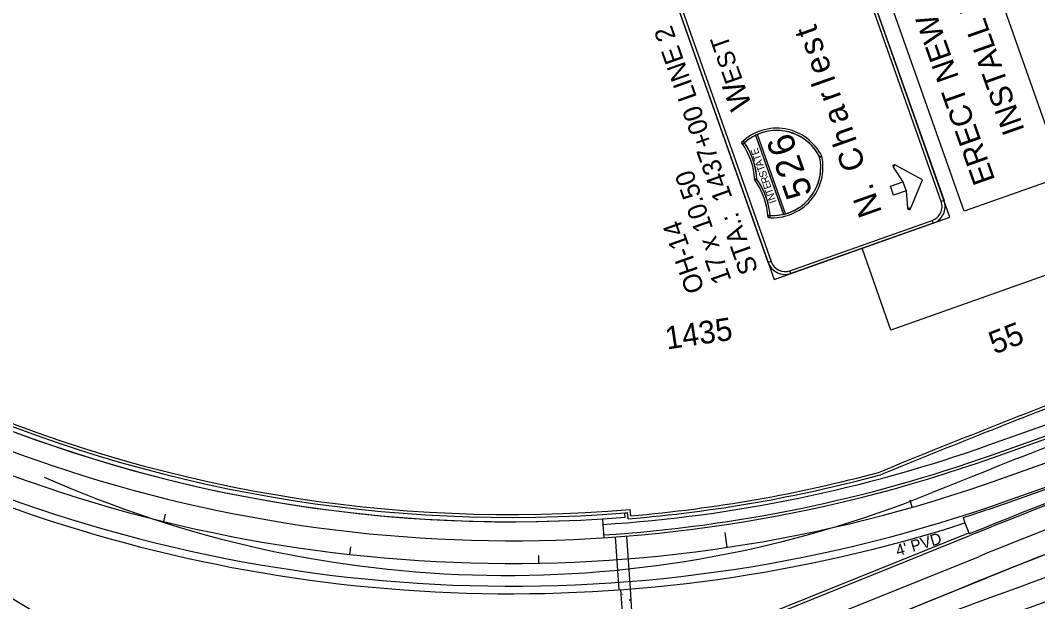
# Model space of a CAD drawing. Extents: x 2338610 to 2351914, y 366540 to 376484.
# Drawn here: x 2349299 to 2349836, y 368231 to 368538 of the extents above; entities that cross this region are included whole.
import ezdxf

# ---------------------------------------------------------------- set-up
doc = ezdxf.new("R2010")
doc.units = 0
for name, color, linetype in [('RD_HC_Cl', 7, 'Continuous'), ('RD_HC_CL_Rel', 7, 'Continuous'), ('RD_PD_ConcMed', 7, 'Continuous'), ('RD_PD_Final_LnLine', 7, 'Continuous'), ('RD_PD_Final_TrvlWay', 7, 'Continuous'), ('RD_PD_FOC', 7, 'Continuous'), ('RD_PD_GR', 7, 'Continuous'), ('RD_PD_MedBWall', 7, 'Continuous'), ('RD_PD_NOISE-WALL-GM', 7, 'Continuous'), ('RD_PD_PaveShd', 7, 'Continuous'), ('RD_PD_SW', 7, 'Continuous'), ('RD_PD_WallCut', 7, 'Continuous'), ('TR PM UNASSIGNED 3', 7, 'Continuous'), ('TR SN EXTRUDED PANEL SIGNS - GROUND MOUNTED', 7, 'Continuous'), ('TR SN EXTRUDED PANEL SIGNS- MOUNTED OVERHEAD', 7, 'Continuous'), ('TR SN UNASSIGNED 7', 7, 'Continuous')]:
    doc.layers.add(name, color=color, linetype=linetype)

msp = doc.modelspace()

# ---------------------------------------------------------------- linework, layer by layer
at = {"layer": 'RD_HC_Cl'}
for centre, radius, start, end in [((2351947.82, 362927.74), 5782.08, 109.588035, 112.01473), ((2351947.82, 362927.74), 5782.08, 109.588035, 112.01473), ((2351947.82, 362927.74), 5782.08, 109.588035, 112.01473), ((2351947.82, 362927.74), 5782.08, 109.588035, 112.01473), ((2351947.82, 362927.74), 5729.58, 109.588035, 115.940729), ((2349555.53, 368844.49), 600, 245.9774, 292.01473), ((2349555.53, 368844.49), 600, 245.9774, 292.01473), ((2349555.53, 368844.49), 600, 245.9774, 292.01473), ((2349555.53, 368844.49), 600, 245.9774, 292.01473)]:
    msp.add_arc(centre, radius, start, end, dxfattribs=at)
at = {"layer": 'RD_HC_CL_Rel'}
msp.add_line((2349816.74, 368295.51), (2350102.51, 368397.2), dxfattribs=at)
for centre, radius, start, end in [((2349557.92, 369022.83), 772, 245.88247, 289.58804), ((2344717.52, 360471.2), 9000, 59.178507, 60.642806)]:
    msp.add_arc(centre, radius, start, end, dxfattribs=at)
at = {"layer": 'RD_PD_ConcMed'}
for p, q in [((2349821.09, 368283.26), (2350106.87, 368384.95)), ((2349796.76, 368275.05), (2349797.67, 368272.19)), ((2349799.79, 368266.92), (2349799.97, 368266.46))]:
    msp.add_line(p, q, dxfattribs=at)
for centre, radius, start, end in [((2351947.82, 362927.74), 5754.58, 109.588035, 111.915714), ((2349557.92, 369022.83), 785, 287.713, 289.58804)]:
    msp.add_arc(centre, radius, start, end, dxfattribs=at)
at = {"layer": 'RD_PD_Final_LnLine'}
for p, q in [((2349815.51, 368295.11), (2350101.29, 368396.8)), ((2349612.85, 368264.87), (2349614.76, 368236.93)), ((2349618.83, 368265.28), (2349620.74, 368237.34)), ((2349685.87, 368206.54), (2349804.82, 368254.4)), ((2349690.35, 368195.41), (2349809.3, 368243.27))]:
    msp.add_line(p, q, dxfattribs=at)
for centre, radius, start, end in [((2349557.92, 369022.83), 772, 245.88247, 289.58804), ((2351947.82, 362927.74), 5741.58, 110.240054, 111.915714), ((2351947.82, 362927.74), 5729.58, 110.561472, 111.915714), ((2351783.35, 362853.29), 5729.58, 109.588035, 115.940729), ((2351783.35, 362853.29), 5717.58, 109.58804, 115.94073)]:
    msp.add_arc(centre, radius, start, end, dxfattribs=at)
at = {"layer": 'RD_PD_Final_TrvlWay'}
for p, q in [((2349812.71, 368306.81), (2350098.11, 368408.37)), ((2349820.76, 368284.2), (2350106.54, 368385.9)), ((2349681.39, 368217.67), (2349800.35, 368265.53))]:
    msp.add_line(p, q, dxfattribs=at)
for centre, radius, start, end in [((2351947.82, 362927.74), 5753.58, 109.588035, 111.915714), ((2351947.82, 362927.74), 5753.58, 109.588035, 111.915714), ((2349557.92, 369022.83), 760, 245.88247, 289.58804), ((2344717.52, 360471.2), 9000, 59.178507, 60.642806), ((2349557.92, 369022.83), 784, 245.88247, 289.58804), ((2344717.52, 360471.2), 8984, 59.178507, 60.415096)]:
    msp.add_arc(centre, radius, start, end, dxfattribs=at)
at = {"layer": 'RD_PD_FOC'}
for p, q in [((2349812.21, 368308.23), (2350098.03, 368409.94)), ((2349680.83, 368219.07), (2349799.79, 368266.92))]:
    msp.add_line(p, q, dxfattribs=at)
msp.add_arc((2349557.92, 369022.83), 758.5, 273.69192, 289.58804, dxfattribs=at)
at = {"layer": 'RD_PD_GR'}
msp.add_arc((2344717.52, 360471.2), 9010, 59.178507, 60.642806, dxfattribs=at)
at = {"layer": 'RD_PD_MedBWall'}
msp.add_line((2349618.15, 368275.25), (2349617.96, 368277.58), dxfattribs=at)
for radius, end in [(747.67, 274.60835), (750, 274.60618)]:
    msp.add_arc((2349557.92, 369022.83), radius, 245.88247, end, dxfattribs=at)
at = {"layer": 'RD_PD_NOISE-WALL-GM'}
for p, q in [((2349621.1, 368276), (2349620.88, 368279.32)), ((2349619.71, 368274.38), (2349619.48, 368277.7))]:
    msp.add_line(p, q, dxfattribs=at)
for centre, radius, start, end in [((2349557.92, 369022.83), 746.17, 245.88247, 274.84011), ((2351947.82, 362927.74), 5802.58, 111.037339, 112.228758), ((2351947.82, 362927.74), 5801.08, 111.052533, 112.229685), ((2349557.92, 369022.83), 751, 274.71968, 285.06835), ((2349557.92, 369022.83), 749.5, 274.83598, 285.06118), ((2349557.92, 369022.83), 747.67, 274.60618, 274.72329)]:
    msp.add_arc(centre, radius, start, end, dxfattribs=at)
at = {"layer": 'RD_PD_PaveShd'}
for p, q in [((2349606.18, 368274.39), (2349606.39, 368271.39)), ((2349797.67, 368272.19), (2349799.79, 368266.92))]:
    msp.add_line(p, q, dxfattribs=at)
for centre, radius, start, end in [((2349557.92, 369022.83), 750, 245.88247, 273.68943), ((2344717.52, 360471.2), 9010, 59.178507, 60.642806), ((2349557.92, 369022.83), 788, 248.85722, 287.713), ((2344717.52, 360471.2), 8974, 59.178507, 60.415096)]:
    msp.add_arc(centre, radius, start, end, dxfattribs=at)
at = {"layer": 'RD_PD_SW'}
for p, q in [((2349810.37, 368313.41), (2350095.99, 368415.05)), ((2349606.39, 368271.39), (2349606.86, 368264.41)), ((2349615.76, 368236.96), (2349616.72, 368222.79)), ((2349620.74, 368237.34), (2349621.94, 368219.82)), ((2349616.91, 368234.66), (2349616.81, 368234.43))]:
    msp.add_line(p, q, dxfattribs=at)
msp.add_lwpolyline([(2349620.25, 368231.41), (2349620.89, 368231.83), (2349621.16, 368231.19), (2349620.25, 368231.41)], dxfattribs=at)
msp.add_arc((2349557.92, 369022.83), 753, 273.69032, 289.58804, dxfattribs=at)
at = {"layer": 'RD_PD_WallCut'}
for radius in [8974, 8971.67]:
    msp.add_arc((2344717.52, 360471.2), radius, 59.178507, 60.415096, dxfattribs=at)
at = {"layer": 'TR SN EXTRUDED PANEL SIGNS - GROUND MOUNTED'}
for p, q in [((2349758.6, 368374.07), (2349743.35, 368417.23)), ((2349844.93, 368404.58), (2349758.6, 368374.07))]:
    msp.add_line(p, q, dxfattribs=at)
at = {"layer": 'TR SN EXTRUDED PANEL SIGNS- MOUNTED OVERHEAD'}
for p, q in [((2349680.61, 368473.8), (2349679.66, 368473.12)), ((2349679.66, 368473.12), (2349680.47, 368472.28)), ((2349687.03, 368476.89), (2349701.76, 368435.2)), ((2349702.9, 368435.49), (2349688.1, 368477.39)), ((2349722.03, 368465.82), (2349720.89, 368465.56)), ((2349720.98, 368465.3), (2349722.03, 368465.82)), ((2349759.72, 368460.12), (2349760.37, 368460.56)), ((2349760.37, 368460.56), (2349760.73, 368461.25)), ((2349687.61, 368454), (2349686.66, 368453.31)), ((2349686.66, 368453.31), (2349687.83, 368453.38)), ((2349786.65, 368442.49), (2349785.18, 368441.97)), ((2349768.18, 368438.45), (2349767.41, 368438.38)), ((2349768.9, 368438.13), (2349768.18, 368438.45)), ((2349693.77, 368434.67), (2349693.66, 368433.51)), ((2349693.66, 368433.51), (2349694.83, 368433.57)), ((2349780.41, 368431.99), (2349780.94, 368430.52)), ((2349695.27, 368410.19), (2349693.79, 368409.67)), ((2349705.76, 368403.95), (2349705.24, 368405.42))]:
    msp.add_line(p, q, dxfattribs=at)
for points in [[(2349797.35, 368436.78), (2349686.04, 368751.7), (2349738.52, 368770.25), (2349849.83, 368455.33)], [(2349789.78, 368433.64), (2349736.64, 368583.99), (2349643.78, 368551.17), (2349696.92, 368400.82), (2349789.78, 368433.64), (2349789.78, 368433.64)], [(2349785.18, 368441.97), (2349738.29, 368574.62), (2349739.77, 368575.14), (2349786.65, 368442.49), (2349785.18, 368441.97), (2349785.18, 368441.97)], [(2349648.38, 368542.84), (2349695.27, 368410.19), (2349693.79, 368409.67), (2349646.91, 368542.32), (2349648.38, 368542.84), (2349648.38, 368542.84)], [(2349702.9, 368435.49), (2349688.1, 368477.39), (2349686.99, 368477), (2349701.8, 368435.1), (2349702.9, 368435.49), (2349702.9, 368435.49)], [(2349775.33, 368453.41), (2349760.73, 368461.25), (2349760.37, 368460.56), (2349759.72, 368460.12), (2349764.9, 368452.42), (2349766.6, 368447.63), (2349767.41, 368438.38), (2349768.18, 368438.45), (2349768.9, 368438.13), (2349775.33, 368453.41), (2349775.33, 368453.41)], [(2349759.96, 368445.28), (2349758.27, 368450.07), (2349764.9, 368452.42), (2349766.6, 368447.63), (2349759.96, 368445.28), (2349759.96, 368445.28)], [(2349705.24, 368405.42), (2349780.41, 368431.99), (2349780.94, 368430.52), (2349705.76, 368403.95), (2349705.24, 368405.42), (2349705.24, 368405.42)]]:
    msp.add_lwpolyline(points, close=True, dxfattribs=at)
for centre, radius, start, end in [((2349698.19, 368454.07), 26.58, 26.222, 134.2188), ((2349698.19, 368454.07), 26.58, 26.222, 134.2188), ((2349698.19, 368454.07), 25.4, 26.222, 134.2188), ((2349698.2, 368454.08), 25.4, 26.5343, 113.4302), ((2349649.19, 368451.21), 37.52, 3.208, 35.7234), ((2349649.19, 368451.21), 37.52, 3.208, 35.7234), ((2349649.19, 368451.21), 38.69, 3.208, 35.7234), ((2349698.19, 368454.07), 25.4, 116.0668, 131.9774), ((2349649.14, 368451.29), 38.69, 3.5799, 34.0624), ((2349696.11, 368459.97), 26.58, 264.7126, 12.7094), ((2349696.11, 368459.97), 26.58, 264.7126, 12.7094), ((2349696.11, 368459.97), 25.4, 264.7126, 12.7094), ((2349696.11, 368459.97), 25.4, 285.5012, 12.3971), ((2349760.37, 368460.56), 0.782, 62.4908, 213.9385), ((2349656.2, 368431.41), 37.52, 3.208, 35.7234), ((2349656.2, 368431.41), 37.52, 3.208, 35.7234), ((2349656.2, 368431.41), 38.69, 3.208, 35.7234), ((2349656.2, 368431.32), 38.69, 4.869, 35.3515), ((2349777.81, 368439.36), 7.82, 289.4655, 19.4657), ((2349777.81, 368439.36), 9.38, 289.4655, 19.4657), ((2349696.11, 368459.97), 25.4, 266.954, 282.8644), ((2349768.18, 368438.45), 0.782, 184.9929, 336.4406), ((2349702.64, 368412.79), 9.38, 199.4659, 289.4655), ((2349702.64, 368412.79), 7.82, 199.4659, 289.4655)]:
    msp.add_arc(centre, radius, start, end, dxfattribs=at)
at = {"layer": 'TR SN UNASSIGNED 7'}
for p, q in [((2349769.8, 368280.48), (2349768.7, 368284.32)), ((2349374.33, 368272.98), (2349375.28, 368276.86)), ((2349672.13, 368259.33), (2349670.95, 368267.24)), ((2349472.73, 368255.55), (2349473.17, 368259.52)), ((2349572.55, 368250.97), (2349572.48, 368254.97))]:
    msp.add_line(p, q, dxfattribs=at)

# ---------------------------------------------------------------- texts
at = {"layer": 'RD_PD_Final_TrvlWay'}
msp.add_text("4' PVD", height=6, rotation=16.3155, dxfattribs=at).set_placement((2349762.17, 368254.58))
at = {"layer": 'TR PM UNASSIGNED 3'}
for s, p in [('STA.:  1437+00 LINE 2', (2349688.56, 368405.5)), ('17 x 10.50', (2349674.41, 368400.5)), ('OH-14', (2349660.27, 368395.51))]:
    msp.add_text(s, height=10, rotation=109.4656, dxfattribs=at).set_placement(p)
at = {"layer": 'TR SN EXTRUDED PANEL SIGNS- MOUNTED OVERHEAD'}
for s, height, rotation, p in [('ERECT NEW CANTILEVER STRUCTURE.', 11.7187, 109.4657, (2349813.77, 368453.35)), ('INSTALL NEW OVERHEAD SIGN(S).', 11.7187, 109.4657, (2349829.35, 368479.61)), ('t', 12.51, 109.4656, (2349720.34, 368531.6)), ('T', 9.38, 109.4656, (2349674.32, 368523.41)), ('s', 12.51, 109.4656, (2349723.84, 368521.7)), ('S', 9.38, 109.4656, (2349677.45, 368514.54)), ('e', 12.51, 109.4656, (2349727.42, 368511.55)), ('E', 9.38, 109.4656, (2349680.39, 368506.22)), ('l', 12.51, 109.4656, (2349729.49, 368505.7)), ('W', 11.73, 109.4656, (2349685.21, 368492.6)), ('r', 12.51, 109.4656, (2349732.52, 368497.13)), ('a', 12.51, 109.4656, (2349736.8, 368485.02)), ('h', 12.51, 109.4656, (2349740.79, 368473.74)), ('6', 14.07, 109.4656, (2349709.26, 368469.11)), ('E', 3.91, 109.4656, (2349689.17, 368467.3)), ('C', 12.51, 109.4656, (2349745.47, 368460.48)), ('T', 3.91, 109.4656, (2349690.21, 368464.37)), ('A', 3.91, 109.4656, (2349691.38, 368461.05)), ('2', 14.07, 109.4656, (2349713.29, 368457.71)), ('T', 3.91, 109.4656, (2349692.26, 368458.58)), ('S', 3.91, 109.4656, (2349693.38, 368455.41)), ('R', 3.91, 109.4656, (2349694.5, 368452.25)), ('E', 3.91, 109.4656, (2349695.53, 368449.31)), ('5', 14.07, 109.4656, (2349717.32, 368446.31)), ('T', 3.91, 109.4656, (2349696.57, 368446.37)), ('N', 3.91, 109.4656, (2349697.69, 368443.21)), ('N', 12.51, 109.4656, (2349754.01, 368436.34)), ('.', 12.51, 109.4656, (2349749.85, 368448.09)), ('I', 3.91, 109.4656, (2349698.2, 368441.77))]:
    msp.add_text(s, height=height, rotation=rotation, dxfattribs=at).set_placement(p)
at = {"layer": 'TR SN UNASSIGNED 7'}
for s, rotation, p in [('1435', 8.5078, (2349640.21, 368363.75)), ('55', 21.3625, (2349813.26, 368361.07))]:
    msp.add_text(s, height=12, rotation=rotation, dxfattribs=at).set_placement(p)

doc.saveas('drawing.dxf')
